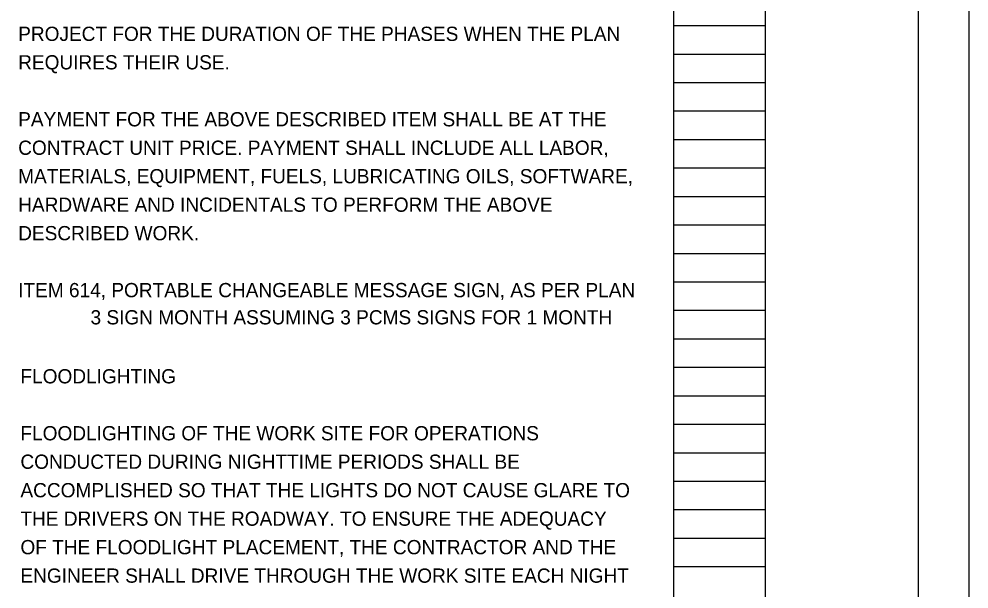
# Model space of a CAD drawing. Extents: x 0 to 34, y 0 to 22.
# Drawn here: x 24.66 to 34, y 5.52 to 11.12 of the extents above; entities that cross this region are included whole.
import ezdxf

# ---------------------------------------------------------------- set-up
doc = ezdxf.new("R2010")
doc.units = 0
for name, color, linetype in [('SH_Border', 7, 'Continuous'), ('SH_Cut_Line', 7, 'Continuous'), ('SH_Data', 7, 'Continuous'), ('SH_Text', 7, 'Continuous')]:
    doc.layers.add(name, color=color, linetype=linetype)

msp = doc.modelspace()

# ---------------------------------------------------------------- linework, layer by layer
at = {"layer": 'SH_Border'}
msp.add_line((32, 0.5), (32, 21.5), dxfattribs=at)
msp.add_lwpolyline([(1.5, 21.5), (33.5, 21.5), (33.5, 0.5), (1.5, 0.5)], close=True, dxfattribs=at)
at = {"layer": 'SH_Cut_Line'}
msp.add_lwpolyline([(0, 0), (34, 0), (34, 22), (0, 22)], close=True, dxfattribs=at)
at = {"layer": 'SH_Data'}
for p, q in [((31.1, 0.98), (31.1, 21.14)), ((32, 0.98), (32, 21.14)), ((31.1, 11.06), (32, 11.06)), ((31.1, 10.78), (32, 10.78)), ((31.1, 10.5), (32, 10.5)), ((31.1, 10.22), (32, 10.22)), ((31.1, 9.94), (32, 9.94)), ((31.1, 9.66), (32, 9.66)), ((31.1, 9.38), (32, 9.38)), ((31.1, 9.1), (32, 9.1)), ((31.1, 8.82), (32, 8.82)), ((31.1, 8.54), (32, 8.54)), ((31.1, 8.26), (32, 8.26)), ((31.1, 7.98), (32, 7.98)), ((31.1, 7.7), (32, 7.7)), ((31.1, 7.42), (32, 7.42)), ((31.1, 7.14), (32, 7.14)), ((31.1, 6.86), (32, 6.86)), ((31.1, 6.58), (32, 6.58)), ((31.1, 6.3), (32, 6.3)), ((31.1, 6.02), (32, 6.02)), ((31.1, 5.74), (32, 5.74))]:
    msp.add_line(p, q, dxfattribs=at)

# ---------------------------------------------------------------- texts
at = {"layer": 'SH_Text'}
for s, p in [('PROJECT FOR THE DURATION OF THE PHASES WHEN THE PLAN', (24.6533, 10.9086)), ('REQUIRES THEIR USE.', (24.6533, 10.6286)), ('PAYMENT FOR THE ABOVE DESCRIBED ITEM SHALL BE AT THE', (24.6533, 10.0686)), ('CONTRACT UNIT PRICE. PAYMENT SHALL INCLUDE ALL LABOR,', (24.6533, 9.7886)), ('MATERIALS, EQUIPMENT, FUELS, LUBRICATING OILS, SOFTWARE,', (24.6533, 9.5086)), ('HARDWARE AND INCIDENTALS TO PERFORM THE ABOVE', (24.6533, 9.2286)), ('DESCRIBED WORK.', (24.6533, 8.9486)), ('ITEM 614, PORTABLE CHANGEABLE MESSAGE SIGN, AS PER PLAN', (24.6533, 8.3886)), ('           3 SIGN MONTH ASSUMING 3 PCMS SIGNS FOR 1 MONTH', (24.7925, 8.1212)), ('FLOODLIGHTING', (24.6755, 7.5414)), ('FLOODLIGHTING OF THE WORK SITE FOR OPERATIONS', (24.6755, 6.9814)), ('CONDUCTED DURING NIGHTTIME PERIODS SHALL BE', (24.6755, 6.7014)), ('ACCOMPLISHED SO THAT THE LIGHTS DO NOT CAUSE GLARE TO', (24.6755, 6.4214)), ('THE DRIVERS ON THE ROADWAY. TO ENSURE THE ADEQUACY', (24.6755, 6.1414)), ('OF THE FLOODLIGHT PLACEMENT, THE CONTRACTOR AND THE', (24.6755, 5.8614)), ('ENGINEER SHALL DRIVE THROUGH THE WORK SITE EACH NIGHT', (24.6755, 5.5814))]:
    msp.add_text(s, height=0.14, dxfattribs=at).set_placement(p)

doc.saveas('drawing.dxf')
